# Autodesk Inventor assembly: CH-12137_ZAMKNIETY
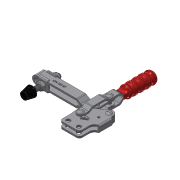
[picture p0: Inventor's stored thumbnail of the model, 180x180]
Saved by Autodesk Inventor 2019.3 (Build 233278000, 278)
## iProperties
Company: Î¢ÈíÖÐ¹ú
Created: 2012-09
Part Number: CH-12137_ZAMKNIETY
Material: Ogólny
Description: STEP AP203
Document SubType Name: Assembly
Designer: CADENGINEERING4
Sending System: SolidWorks 2010
Preprocessor: SwSTEP 2.0
Title: CH-12137.STEP
Author: Î¢ÈíÓÃ»§
Revision Number: ÈÎºÎ
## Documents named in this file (12)
- D:\Vault_2016\Projekty\NASZ KATALOG\CLAMPTEK\STRONA\Vertical toggle clamp\CH-12137\CH-12137_ZAMKNIETY.iam
- D:\Vault_2016\Projekty\NASZ KATALOG\CLAMPTEK\STEP FILES\Vertical toggle clamp\CH-12137\CH-FC-56212 SPINDLE SUPPLIED.ipt
- D:\Vault_2016\Projekty\NASZ KATALOG\CLAMPTEK\STEP FILES\Vertical toggle clamp\CH-12137\CH-12130-05.ipt
- D:\Vault_2016\Projekty\NASZ KATALOG\CLAMPTEK\STEP FILES\Vertical toggle clamp\CH-12137\CH-12130-07.ipt
- D:\Vault_2016\Projekty\NASZ KATALOG\CLAMPTEK\STEP FILES\Vertical toggle clamp\CH-12137\CH-12130-06.ipt
- D:\Vault_2016\Projekty\NASZ KATALOG\CLAMPTEK\STEP FILES\Vertical toggle clamp\CH-12137\CH-12145-01 STRAIGHT BASE.ipt
- D:\Vault_2016\Projekty\NASZ KATALOG\CLAMPTEK\STEP FILES\Vertical toggle clamp\CH-12137\CH-FC-56212 Nut.ipt
- D:\Vault_2016\Projekty\NASZ KATALOG\CLAMPTEK\STEP FILES\Vertical toggle clamp\CH-12137\CH-FW-516.ipt
- D:\Vault_2016\Projekty\NASZ KATALOG\CLAMPTEK\STEP FILES\Vertical toggle clamp\CH-12137\CH-12130-04 CONNECTING-PLATE.ipt
- D:\Vault_2016\Projekty\NASZ KATALOG\CLAMPTEK\STEP FILES\Vertical toggle clamp\CH-12137\CH-12137-02 LONG U-BAR.ipt
- D:\Vault_2016\Projekty\NASZ KATALOG\CLAMPTEK\STEP FILES\Vertical toggle clamp\CH-12137\CH-12130-08.ipt
- D:\Vault_2016\Projekty\NASZ KATALOG\CLAMPTEK\STEP FILES\Vertical toggle clamp\CH-12137\CH-12130-03 STRAIGHT HANDLE.ipt
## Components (15 placed, 15 different names)
1. CH-FC-56212 SPINDLE SUPPLIED_1
2. CH-12130-05_2
3. CH-12130-07_3
4. CH-12130-06_4
5. CH-12130-06_5
6. CH-12145-01 STRAIGHT BASE_6
7. CH-FC-56212 Nut_7
8. CH-FW-516_8
9. CH-12130-04 CONNECTING-PLATE_9
10. CH-12137-02 LONG U-BAR_10
11. CH-FW-516_11
12. CH-12130-08_12
13. CH-FC-56212 Nut_13
14. CH-12130-03 STRAIGHT HANDLE_14
15. CH-12130-08_15
